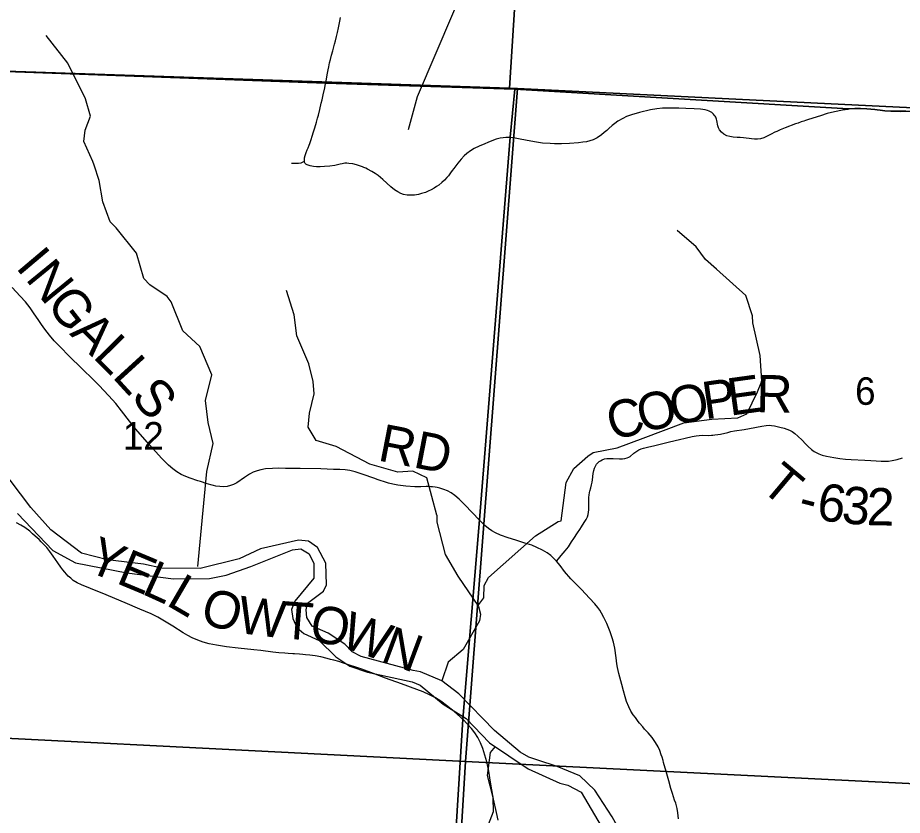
# Model space of a CAD drawing. Extents: x 21.4 to 65.3, y 4 to 26.
# Drawn here: x 24.526 to 25.873, y 19.377 to 20.591 of the extents above; entities that cross this region are included whole.
import ezdxf

# ---------------------------------------------------------------- set-up
doc = ezdxf.new("R2010")
doc.units = 0
for name, color, linetype in [('Default', 7, 'Continuous'), ('GM_X_County_Road', 7, 'Continuous'), ('GM_X_County_Road_Text', 7, 'Continuous'), ('GM_X_Major_River', 7, 'Continuous'), ('GM_X_Minor_River', 7, 'Continuous'), ('GM_X_Section', 7, 'Continuous'), ('GM_X_Section_Text', 7, 'Continuous'), ('GM_X_Township_Road', 7, 'Continuous'), ('GM_X_Township_Road_Text', 7, 'Continuous')]:
    doc.layers.add(name, color=color, linetype=linetype)

msp = doc.modelspace()

# ---------------------------------------------------------------- linework, layer by layer
at = {"layer": 'Default'}
for points in [[(23.5473, 24.8542), (23.5473, 20.5568), (23.9671, 20.5321), (24.2595, 20.5181), (24.9947, 20.491), (25.2828, 20.4818), (25.7909, 20.4519), (25.8002, 20.4525), (25.809, 20.4526), (25.8187, 20.4522), (25.831, 20.4509), (25.8341, 20.4506), (25.8391, 20.4499), (25.8459, 20.4493), (25.8552, 20.4488), (25.869, 20.4484), (25.878, 20.4484)], [(25.878, 20.4484), (25.869, 20.4484), (25.8552, 20.4488), (25.8459, 20.4493), (25.8391, 20.4499), (25.8341, 20.4506), (25.831, 20.4509), (25.8187, 20.4522), (25.809, 20.4526), (25.8002, 20.4525), (25.7909, 20.4519), (25.2828, 20.4818), (25.2761, 20.4088), (25.229, 19.8268), (25.2037, 19.5236), (25.1319, 18.358), (25.1151, 18.0542), (28.6177, 18.0542)]]:
    msp.add_lwpolyline(points, dxfattribs=at)
msp.add_lwpolyline([(23.5473, 20.5568), (23.5473, 18.0542), (25.1151, 18.0542), (25.1319, 18.358), (25.2037, 19.5236), (25.229, 19.8268), (25.2761, 20.4088), (25.2828, 20.4818), (24.9947, 20.491), (24.2595, 20.5181), (23.9671, 20.5321)], close=True, dxfattribs=at)
at = {"layer": 'GM_X_County_Road'}
for points in [[(24.9949, 20.4905), (24.9958, 20.4947), (24.9981, 20.5063), (24.9991, 20.5115), (25, 20.5162), (25.0012, 20.5221), (25.0023, 20.5271), (25.0041, 20.5339), (25.0058, 20.5403), (25.0069, 20.5445), (25.0087, 20.5507), (25.0101, 20.5558), (25.0117, 20.5623), (25.0132, 20.5685), (25.0146, 20.5752), (25.0156, 20.5804), (25.0167, 20.5856), (25.0178, 20.5911)], [(25.2763, 20.4083), (25.2748, 20.4085), (25.2692, 20.4086), (25.265, 20.4082), (25.2605, 20.4074), (25.2546, 20.4059), (25.2478, 20.4035), (25.242, 20.401), (25.2373, 20.3991), (25.2287, 20.3955), (25.2209, 20.3916), (25.2156, 20.3883), (25.21, 20.3842), (25.2058, 20.3805), (25.2011, 20.3755), (25.196, 20.3692), (25.19, 20.3613), (25.1878, 20.3583), (25.1853, 20.3549), (25.1819, 20.3503), (25.1795, 20.3475), (25.1757, 20.3435), (25.1721, 20.3401), (25.1673, 20.3362), (25.1638, 20.3338), (25.1601, 20.3314), (25.1559, 20.329), (25.1509, 20.3266), (25.1468, 20.325), (25.141, 20.3231), (25.1362, 20.3218), (25.1302, 20.3208), (25.1247, 20.3205), (25.1191, 20.3209), (25.1137, 20.322), (25.1097, 20.3234), (25.1047, 20.3258), (25.1001, 20.3288), (25.0944, 20.3335), (25.0821, 20.3448), (25.0748, 20.3506), (25.0718, 20.3529), (25.0702, 20.3538), (25.0654, 20.3567), (25.059, 20.3605), (25.0561, 20.3618), (25.0533, 20.3631), (25.051, 20.3641), (25.0451, 20.3661), (25.0422, 20.3671), (25.0367, 20.3684), (25.0305, 20.3691), (25.0271, 20.3693), (25.0243, 20.3692), (25.0204, 20.3686), (25.0173, 20.368), (25.0093, 20.366), (25.0016, 20.3649), (24.9935, 20.3643), (24.9869, 20.364), (24.9813, 20.364), (24.9765, 20.3644), (24.9713, 20.3652), (24.9668, 20.3669), (24.965, 20.3681), (24.9639, 20.3691), (24.9634, 20.37), (24.963, 20.3712), (24.9628, 20.3724), (24.9628, 20.3751), (24.963, 20.3777), (24.964, 20.3811), (24.9656, 20.3856), (24.9672, 20.3896), (24.9686, 20.3929), (24.97, 20.3967), (24.971, 20.3993), (24.9731, 20.4056), (24.9748, 20.4105), (24.9768, 20.4173), (24.9787, 20.4234), (24.9812, 20.4319), (24.9828, 20.4377), (24.9842, 20.4427), (24.9862, 20.4512), (24.9885, 20.4609), (24.9896, 20.4658), (24.9913, 20.4736), (24.9936, 20.4839), (24.9949, 20.4905)], [(25.7899, 20.4513), (25.7814, 20.45), (25.7696, 20.4475), (25.7584, 20.4448), (25.7481, 20.4415), (25.7298, 20.4358), (25.7251, 20.4342), (25.7227, 20.4334), (25.7186, 20.4321), (25.7139, 20.4305), (25.7098, 20.4291), (25.6941, 20.4233), (25.6867, 20.4201), (25.6815, 20.4177), (25.6786, 20.4164), (25.6728, 20.4135), (25.667, 20.4104), (25.6617, 20.4078), (25.6568, 20.4063), (25.652, 20.4058), (25.6477, 20.4059), (25.6431, 20.4065), (25.6397, 20.4069), (25.635, 20.4076), (25.6307, 20.4082), (25.6259, 20.4085), (25.6211, 20.4087), (25.6152, 20.4092), (25.6101, 20.41), (25.6054, 20.4112), (25.6011, 20.4134), (25.5975, 20.4166), (25.5946, 20.4203), (25.5929, 20.4232), (25.5917, 20.4264), (25.5905, 20.4342), (25.5896, 20.4366), (25.5886, 20.4395), (25.5876, 20.4411), (25.5865, 20.4426), (25.5853, 20.4441), (25.5825, 20.4465), (25.5786, 20.4488), (25.5762, 20.4497), (25.5726, 20.4507), (25.5656, 20.4517), (25.5559, 20.4521), (25.5432, 20.4526), (25.5326, 20.453), (25.5172, 20.4533), (25.5077, 20.4531), (25.499, 20.4521), (25.4893, 20.4504), (25.4728, 20.4465), (25.4606, 20.4431), (25.4576, 20.4421), (25.453, 20.4403), (25.4474, 20.4374), (25.4398, 20.4332), (25.4352, 20.4298), (25.4311, 20.4266), (25.4259, 20.4223), (25.4228, 20.4194), (25.4191, 20.416), (25.415, 20.4127), (25.4081, 20.4081), (25.4021, 20.4052), (25.397, 20.4033), (25.3918, 20.4021), (25.3864, 20.4013), (25.3797, 20.4004), (25.366, 20.3993), (25.3541, 20.399), (25.3431, 20.3989), (25.3365, 20.3992), (25.3252, 20.4001), (25.313, 20.4018), (25.2991, 20.4044), (25.2912, 20.4061), (25.2834, 20.4075), (25.2763, 20.4083)], [(25.9041, 20.4509), (25.9009, 20.4495), (25.8962, 20.4482), (25.8902, 20.448), (25.8782, 20.4479), (25.8693, 20.4478), (25.8554, 20.4483), (25.8461, 20.4487), (25.8393, 20.4494), (25.8344, 20.45), (25.8312, 20.4504), (25.8189, 20.4517), (25.8092, 20.4521), (25.8004, 20.452), (25.7911, 20.4514), (25.7899, 20.4513)], [(24.7135, 19.9564), (24.7128, 19.9572), (24.7063, 19.9647), (24.6966, 19.9768), (24.6845, 19.9926), (24.6756, 20.0037), (24.6654, 20.0155), (24.6573, 20.024), (24.6508, 20.0308), (24.6407, 20.0409), (24.6251, 20.056), (24.6038, 20.0769), (24.592, 20.0889), (24.5822, 20.0992), (24.5748, 20.1076), (24.5711, 20.1123), (24.5676, 20.1169), (24.5626, 20.1241), (24.5576, 20.1313), (24.5514, 20.1404), (24.5454, 20.1494), (24.5382, 20.1585), (24.5303, 20.1673), (24.5179, 20.1804)], [(25.2292, 19.8263), (25.2068, 19.8497), (25.1984, 19.8579), (25.1918, 19.8637), (25.1862, 19.8677), (25.1807, 19.8708), (25.1749, 19.8731), (25.1689, 19.8749), (25.1647, 19.8758), (25.1616, 19.8764), (25.1579, 19.8768), (25.1548, 19.8771), (25.1506, 19.8773), (25.1481, 19.8773), (25.1401, 19.8771), (25.1308, 19.8771), (25.1172, 19.8779), (25.1129, 19.8783), (25.105, 19.8795), (25.1025, 19.8799), (25.0971, 19.8809), (25.0905, 19.8826), (25.0846, 19.8844), (25.0781, 19.8865), (25.0752, 19.8876), (25.0682, 19.8901), (25.0524, 19.8958), (25.04, 19.8998), (25.032, 19.9016), (25.0246, 19.9026), (25.0165, 19.9031), (25.0072, 19.9035), (24.988, 19.9041), (24.9563, 19.9046), (24.934, 19.905), (24.9234, 19.9052), (24.9141, 19.905), (24.9035, 19.9042), (24.8967, 19.903), (24.8907, 19.9013), (24.8849, 19.899), (24.8794, 19.896), (24.8715, 19.891), (24.8599, 19.8829), (24.8551, 19.8803), (24.8505, 19.8787), (24.8451, 19.8776), (24.8396, 19.8771), (24.8341, 19.8772), (24.828, 19.8781), (24.8244, 19.8789), (24.8226, 19.8793), (24.8149, 19.8815), (24.8049, 19.8848), (24.8008, 19.8862), (24.789, 19.8902), (24.7821, 19.8928), (24.7754, 19.8959), (24.7685, 19.8999), (24.7625, 19.9044), (24.756, 19.91), (24.7459, 19.9201), (24.7318, 19.9358), (24.7235, 19.9451), (24.7135, 19.9564)], [(25.532, 19.3715), (25.5311, 19.3808), (25.5299, 19.3876), (25.5277, 19.3954), (25.5261, 19.4), (25.5228, 19.4103), (25.5205, 19.4181), (25.5173, 19.4297), (25.5133, 19.4435), (25.5093, 19.4573), (25.5085, 19.4603), (25.5069, 19.4655), (25.5058, 19.4692), (25.5035, 19.4757), (25.5009, 19.4814), (25.4971, 19.4878), (25.4917, 19.4953), (25.4857, 19.5024), (25.4804, 19.5084), (25.4775, 19.5117), (25.4728, 19.5173), (25.4708, 19.5197), (25.4664, 19.5257), (25.4632, 19.5301), (25.4596, 19.5358), (25.4565, 19.5419), (25.4531, 19.5505), (25.4508, 19.5575), (25.4484, 19.5665), (25.446, 19.5761), (25.4414, 19.5929), (25.4393, 19.6019), (25.4383, 19.6074), (25.437, 19.6166), (25.4349, 19.6314), (25.433, 19.6405), (25.4311, 19.6471), (25.4278, 19.6565), (25.423, 19.6687), (25.4186, 19.6783), (25.415, 19.6849), (25.4121, 19.689), (25.4093, 19.6931), (25.4047, 19.6989), (25.3968, 19.7077), (25.3842, 19.7207), (25.3759, 19.7291), (25.3681, 19.7371), (25.3584, 19.7483), (25.3517, 19.757), (25.3462, 19.7639), (25.3424, 19.7681), (25.3377, 19.7723), (25.3321, 19.7763), (25.3252, 19.7804), (25.3163, 19.7848), (25.3088, 19.7879), (25.2982, 19.7914), (25.2845, 19.7956), (25.2727, 19.7994), (25.261, 19.8036), (25.2537, 19.8069), (25.2478, 19.8102), (25.2427, 19.8136), (25.2375, 19.818), (25.2292, 19.8263)]]:
    msp.add_lwpolyline(points, dxfattribs=at)
at = {"layer": 'GM_X_Major_River'}
for points in [[(24.5463, 19.8457), (24.4833, 19.9287)], [(25.3472, 19.4513), (25.3178, 19.4608), (25.3041, 19.4653), (25.2909, 19.4732), (25.2522, 19.5061), (25.1979, 19.5621), (25.1721, 19.5817), (25.1396, 19.5956), (25.1282, 19.5975), (25.049, 19.6189), (25.0354, 19.626), (25.0244, 19.6374), (24.999, 19.6544), (24.9748, 19.6649), (24.9664, 19.6782), (24.9656, 19.6899), (24.9675, 19.6998), (24.992, 19.7184), (24.9962, 19.7279), (24.9954, 19.7609), (24.9828, 19.7844), (24.9692, 19.7942), (24.9536, 19.796), (24.8958, 19.7826), (24.8636, 19.7673), (24.8042, 19.7524), (24.7456, 19.753), (24.7179, 19.759), (24.663, 19.766), (24.6237, 19.7761), (24.577, 19.8116), (24.5463, 19.8457)], [(24.5262, 19.8365), (24.5801, 19.7802), (24.6142, 19.7613), (24.6926, 19.746), (24.7634, 19.7371), (24.8183, 19.7373), (24.8436, 19.7426), (24.8814, 19.7556), (24.9446, 19.7812), (24.9571, 19.7828), (24.97, 19.7748), (24.9772, 19.7605), (24.9772, 19.7377), (24.9482, 19.7028), (24.9433, 19.6902), (24.9452, 19.6766), (24.9513, 19.663), (24.9619, 19.6535), (24.985, 19.643), (25.0104, 19.6184), (25.0317, 19.604), (25.0589, 19.595), (25.1267, 19.5804), (25.1389, 19.5752), (25.1741, 19.5464), (25.209, 19.5242), (25.2446, 19.4875), (25.303, 19.4479), (25.3515, 19.426), (25.3637, 19.4231)], [(25.8861, 19.1677), (25.8199, 19.1002), (25.7702, 19.0619), (25.6844, 18.9806), (25.6577, 18.9626), (25.6441, 18.9591), (25.6289, 18.9572), (25.6161, 18.9597), (25.6047, 18.9684), (25.6008, 18.9813), (25.5983, 19.0215), (25.6085, 19.1042), (25.608, 19.1251), (25.5945, 19.1648), (25.5785, 19.1879), (25.5273, 19.2153), (25.5152, 19.2247), (25.4916, 19.2519), (25.4698, 19.2927), (25.4552, 19.3313), (25.4311, 19.3748), (25.4045, 19.4152), (25.3821, 19.4371), (25.3472, 19.4513)], [(25.3637, 19.4231), (25.3837, 19.4125), (25.4348, 19.3259), (25.4666, 19.2517), (25.4841, 19.2279), (25.5069, 19.2068), (25.5638, 19.1753), (25.576, 19.1636), (25.5844, 19.1416), (25.5884, 19.1075), (25.5882, 19.0832), (25.576, 19.027), (25.5767, 18.9747), (25.5855, 18.9402), (25.5833, 18.9277), (25.5781, 18.9151), (25.5918, 18.9114), (25.6261, 18.9196), (25.6661, 18.9388), (25.6914, 18.9549), (25.7403, 18.9995), (25.8449, 19.0958), (25.9201, 19.1747)]]:
    msp.add_lwpolyline(points, dxfattribs=at)
at = {"layer": 'GM_X_Minor_River'}
for points in [[(25.2185, 20.8293), (25.2305, 20.7698), (25.2167, 20.663), (25.1342, 20.4706), (25.1208, 20.42)], [(24.8005, 19.7557), (24.8143, 19.9003), (24.8238, 19.9429), (24.8162, 19.9748), (24.8121, 20.0082), (24.8219, 20.0474), (24.8038, 20.0904), (24.778, 20.1143), (24.7602, 20.1584), (24.7538, 20.1667), (24.7276, 20.1842), (24.7185, 20.1937), (24.7075, 20.2325), (24.6761, 20.2712), (24.6674, 20.2803), (24.656, 20.3104), (24.6503, 20.3431), (24.6428, 20.3662), (24.6409, 20.3719), (24.6272, 20.4023), (24.6291, 20.4195), (24.6375, 20.4408), (24.6295, 20.4674), (24.6026, 20.5217), (24.5697, 20.5639)], [(25.3534, 19.8252), (25.3613, 19.8837), (25.3727, 19.905), (25.3939, 19.9237), (25.4023, 19.9294), (25.4387, 19.9363), (25.4781, 19.9508), (25.5403, 19.9744), (25.5827, 19.9801), (25.6225, 19.9817), (25.6358, 19.9882), (25.6521, 20.0217), (25.6586, 20.0376), (25.6563, 20.0768), (25.6453, 20.1266), (25.6446, 20.1372), (25.6344, 20.168), (25.59, 20.2083), (25.5733, 20.2231), (25.5589, 20.2421), (25.5298, 20.2668)], [(25.1643, 19.8338), (25.149, 19.8904), (25.1278, 19.9006), (25.1051, 19.8994), (25.0622, 19.9116), (25.0111, 19.9381), (24.9807, 19.9476), (24.9686, 19.9677), (24.9705, 19.989), (24.9777, 20.0183), (24.9762, 20.0373), (24.9694, 20.0639), (24.9512, 20.1065), (24.9471, 20.1384), (24.9353, 20.1757)], [(25.1643, 19.8338), (25.1644, 19.8231), (25.1772, 19.7738), (25.196, 19.7408), (25.2278, 19.6947), (25.2309, 19.6833), (25.2291, 19.673), (25.2043, 19.6292), (25.1816, 19.6101), (25.1721, 19.5817)], [(25.2269, 19.6959), (25.2357, 19.708), (25.2363, 19.727), (25.2427, 19.7392), (25.3144, 19.8022), (25.3488, 19.824), (25.3534, 19.8252)], [(25.2529, 19.4818), (25.2455, 19.4726), (25.2407, 19.4376), (25.2493, 19.4043), (25.2502, 19.3826), (25.2423, 19.3625), (25.2031, 19.3266), (25.1333, 19.256), (25.0683, 19.2105), (25.0174, 19.1661)]]:
    msp.add_lwpolyline(points, dxfattribs=at)
at = {"layer": 'GM_X_Section'}
for points in [[(25.3384, 21.4821), (25.275, 20.4836), (24.2227, 20.5192), (24.2858, 21.5075), (24.7985, 21.5074)], [(26.3977, 21.4352), (26.3809, 21.1738), (26.3352, 20.4317), (25.2871, 20.4832), (25.275, 20.4836), (25.3384, 21.4821)], [(24.2227, 20.5192), (25.275, 20.4836), (25.2871, 20.4832), (25.208, 19.459), (24.1671, 19.5117)], [(25.2871, 20.4832), (26.3352, 20.4317), (26.3235, 20.1926), (26.3057, 19.938), (26.289, 19.6776), (26.2711, 19.4096), (26.2708, 19.4063), (25.208, 19.459)], [(24.1671, 19.5117), (25.208, 19.459), (25.1472, 18.4529), (24.1059, 18.5148)], [(25.208, 19.459), (26.2708, 19.4063), (26.2556, 19.168), (26.2403, 18.9172), (26.2238, 18.6579), (26.208, 18.4108), (25.1472, 18.4529)]]:
    msp.add_lwpolyline(points, close=True, dxfattribs=at)
at = {"layer": 'GM_X_Township_Road'}
for points in [[(24.9429, 20.3696), (24.9465, 20.3694), (24.949, 20.3694), (24.9536, 20.3695), (24.9576, 20.37), (24.96, 20.3709), (24.9628, 20.3724)], [(25.3462, 19.7639), (25.3496, 19.7676), (25.3537, 19.7722), (25.3596, 19.7793), (25.3644, 19.7858), (25.3693, 19.793), (25.3727, 19.7982), (25.3782, 19.8071), (25.3817, 19.8122), (25.3842, 19.8158), (25.3887, 19.8225), (25.3915, 19.8273), (25.3933, 19.8313), (25.3945, 19.8348), (25.3952, 19.8384), (25.3955, 19.8421), (25.3954, 19.8564), (25.3957, 19.8614), (25.396, 19.8644), (25.3967, 19.8681), (25.3972, 19.8705), (25.3984, 19.8753), (25.3997, 19.8801), (25.4005, 19.8838), (25.4012, 19.8874), (25.4023, 19.8973), (25.4031, 19.9016), (25.4042, 19.9051), (25.4058, 19.9086), (25.4074, 19.9112), (25.4089, 19.9131), (25.4112, 19.9153), (25.4132, 19.9167), (25.4159, 19.9182), (25.4194, 19.9194), (25.4231, 19.92), (25.4268, 19.9202), (25.4324, 19.92), (25.4423, 19.9194), (25.4467, 19.9195), (25.4504, 19.9199), (25.454, 19.9208), (25.4562, 19.9219), (25.4583, 19.9232), (25.464, 19.928), (25.4685, 19.9313), (25.4717, 19.9332), (25.4751, 19.9347), (25.4786, 19.9359), (25.4847, 19.9374), (25.4962, 19.94), (25.4998, 19.9409), (25.5022, 19.9414), (25.5185, 19.9454), (25.5337, 19.9488), (25.5421, 19.9508), (25.553, 19.9536), (25.5591, 19.9547), (25.5634, 19.9551), (25.5683, 19.9553), (25.5783, 19.9552), (25.582, 19.9553), (25.5845, 19.9556), (25.5875, 19.9558), (25.5918, 19.9564), (25.5961, 19.9571), (25.607, 19.9598), (25.6118, 19.961), (25.6173, 19.9621), (25.632, 19.9643), (25.64, 19.9656), (25.6589, 19.9691), (25.6656, 19.9703), (25.6699, 19.9707), (25.6736, 19.9705), (25.6779, 19.9698), (25.6864, 19.9679), (25.6929, 19.9661), (25.697, 19.9647), (25.701, 19.963), (25.7048, 19.961), (25.7088, 19.9582), (25.7135, 19.9542), (25.72, 19.9478), (25.7251, 19.9425), (25.7294, 19.9382), (25.7346, 19.9337), (25.7386, 19.9308), (25.7423, 19.9285), (25.7457, 19.9269), (25.7504, 19.9253), (25.7574, 19.9237), (25.7686, 19.9218), (25.7773, 19.9202), (25.7859, 19.9189), (25.7946, 19.9184), (25.8154, 19.9176), (25.8246, 19.917), (25.8328, 19.9164), (25.8403, 19.9158), (25.8463, 19.9158), (25.8514, 19.9161), (25.8572, 19.9171), (25.8647, 19.9187), (25.8728, 19.921)], [(25.2046, 19.5224), (25.2039, 19.523), (25.2003, 19.5266), (25.1907, 19.5349), (25.1792, 19.5441), (25.1703, 19.5507), (25.1621, 19.5559), (25.1531, 19.5604), (25.1433, 19.5648), (25.1338, 19.5683), (25.1103, 19.5769), (25.086, 19.586), (25.068, 19.5927), (25.05, 19.5993), (25.0221, 19.6088), (25.0149, 19.611), (25.0075, 19.6131), (25.0025, 19.6144), (24.9973, 19.6158), (24.9877, 19.6181), (24.9792, 19.6197), (24.9712, 19.6206), (24.9645, 19.6214), (24.9602, 19.6218), (24.9553, 19.6222), (24.9479, 19.6227), (24.9454, 19.6229), (24.938, 19.6234), (24.9331, 19.6237), (24.924, 19.6244), (24.9149, 19.6253), (24.8967, 19.6277), (24.8856, 19.6287), (24.8621, 19.6313), (24.8442, 19.6335), (24.8288, 19.6358), (24.8178, 19.638), (24.8088, 19.6404), (24.8006, 19.6434), (24.7921, 19.6473), (24.7854, 19.6509), (24.7784, 19.6546), (24.7627, 19.6647), (24.7501, 19.6727), (24.7398, 19.6786), (24.7297, 19.6837), (24.7123, 19.6907), (24.6898, 19.7003), (24.655, 19.7153), (24.6435, 19.7198), (24.6312, 19.7246), (24.6272, 19.7263), (24.6237, 19.7276), (24.617, 19.7309), (24.6111, 19.7346), (24.6072, 19.7377), (24.6035, 19.741), (24.5981, 19.7469), (24.5951, 19.7508), (24.592, 19.7547), (24.5874, 19.7614), (24.5842, 19.7661), (24.5806, 19.7713), (24.5755, 19.7783), (24.5706, 19.7846), (24.5665, 19.7892), (24.5624, 19.7932), (24.559, 19.7966), (24.5531, 19.8021), (24.5491, 19.8056), (24.5448, 19.8094), (24.5374, 19.8149), (24.5312, 19.8188), (24.5246, 19.8222)], [(25.2577, 19.3696), (25.2549, 19.3811), (25.2505, 19.4018), (25.2494, 19.4073), (25.2459, 19.4275), (25.2432, 19.444), (25.2402, 19.4584), (25.2375, 19.4686), (25.2343, 19.4787), (25.2305, 19.4875), (25.2265, 19.4955), (25.2221, 19.5028), (25.2169, 19.5094), (25.21, 19.5169), (25.2046, 19.5224)]]:
    msp.add_lwpolyline(points, dxfattribs=at)

# ---------------------------------------------------------------- texts
at = {"layer": 'GM_X_County_Road_Text'}
for s, height, rotation, p in [('I', 0.0568, 310.1619, (24.5222, 20.2108)), ('N', 0.0568, 309.1815, (24.5371, 20.1932)), ('G', 0.0568, 307.9566, (24.5685, 20.1547)), ('A', 0.0568, 315.0572, (24.6043, 20.1095)), ('L', 0.0568, 314.6167, (24.6396, 20.0743)), ('L', 0.0568, 312.4173, (24.6691, 20.0444)), ('S', 0.0568, 309.6705, (24.6973, 20.0136)), ('RD', 0.05682, 348.9822, (25.0729, 19.9173))]:
    msp.add_text(s, height=height, rotation=rotation, dxfattribs=at).set_placement(p)
at = {"layer": 'GM_X_Section_Text'}
for s, height, p in [('6', 0.0419, (25.8007, 20.0017)), ('12', 0.04186, (24.6865, 19.9336))]:
    msp.add_text(s, height=height, rotation=0, dxfattribs=at).set_placement(p)
at = {"layer": 'GM_X_Township_Road_Text'}
for s, rotation, p in [('E', 7.848, (25.6103, 19.985)), ('R', 358.7197, (25.65, 19.9907)), ('O', 11.0106, (25.5241, 19.9701)), ('P', 8.2655, (25.5725, 19.9795)), ('O', 13.1448, (25.476, 19.9589)), ('C', 15.1618, (25.4315, 19.9468)), ('T', 319.9519, (25.6547, 19.8744)), ('6', 351.5629, (25.7405, 19.8274)), ('3', 355.2612, (25.7791, 19.8218)), ('2', 358.8557, (25.8179, 19.8187)), ('-', 345.4327, (25.7115, 19.8346)), ('Y', 337.4034, (24.6286, 19.7503)), ('E', 337.3228, (24.6747, 19.7311)), ('L', 335.5532, (24.7135, 19.7149)), ('L', 329.6834, (24.7508, 19.698)), ('O', 344.1316, (24.8019, 19.6704)), ('W', 352.8935, (24.8593, 19.6549)), ('T', 355.6405, (24.9276, 19.6464)), ('O', 349.1734, (24.9683, 19.6434)), ('W', 340.6512, (25.0152, 19.6346)), ('N', 339.536, (25.0771, 19.6129))]:
    msp.add_text(s, height=0.0568, rotation=rotation, dxfattribs=at).set_placement(p)

doc.saveas('drawing.dxf')
